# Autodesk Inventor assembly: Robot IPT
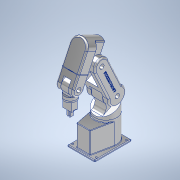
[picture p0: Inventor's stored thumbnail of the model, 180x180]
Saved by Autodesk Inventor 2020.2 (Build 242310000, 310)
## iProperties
Created: 2018-07
Part Number: Robot IPT
Document SubType Name: Assembly
Designer: Power User
Mass: 35329.7 g
Surface Area: 8047.72 cm^2
Volume: 13085.1 cm^3
Density: 2.7 g/cm^3
Author: Power User
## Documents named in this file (10)
- C:\Users\thira\OneDrive\เดสก์ท็อป\INV-01 Intro to Modeling_2020\Robot IPT\Robot IPT.iam
- C:\Users\thira\OneDrive\เดสก์ท็อป\INV-01 Intro to Modeling_2020\Robot IPT\Robot-Base-Model-A.ipt
- C:\Users\thira\OneDrive\เดสก์ท็อป\INV-01 Intro to Modeling_2020\Robot IPT\Robot-Axis1-1.ipt
- C:\Users\thira\OneDrive\เดสก์ท็อป\INV-01 Intro to Modeling_2020\Robot IPT\Robot-Axis1-2.ipt
- C:\Users\thira\OneDrive\เดสก์ท็อป\INV-01 Intro to Modeling_2020\Robot IPT\Robot-Axis1-3.ipt
- C:\Users\thira\OneDrive\เดสก์ท็อป\INV-01 Intro to Modeling_2020\Robot IPT\Robot-Axis1-4.ipt
- C:\Users\thira\OneDrive\เดสก์ท็อป\INV-01 Intro to Modeling_2020\Robot IPT\Robot-Axis1-5.ipt
- C:\Users\thira\OneDrive\เดสก์ท็อป\INV-01 Intro to Modeling_2020\Robot IPT\Robot-Axis1-6.ipt
- C:\Users\thira\OneDrive\เดสก์ท็อป\INV-01 Intro to Modeling_2020\Robot IPT\Robot-Clamp.ipt
- C:\Users\thira\OneDrive\เดสก์ท็อป\INV-01 Intro to Modeling_2020\Robot IPT\Robot-Clamp-Mount.ipt
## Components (10 placed, 9 different names)
1. Robot-Base-Model-A:1 — Rotational:1
2. Robot-Axis1-1:1 — Rotational:1, Rotational:2
3. Robot-Axis1-2:1 — Rotational:2, Rotational:3
4. Robot-Clamp:1 — Mate:1, Mate:2, Slider:1, Mate:5
5. Robot-Clamp-Mount:1 — Rotational:6, Mate:1, Mate:2, Mate:3, Mate:4, Slider:1, Slider:2, Mate:5, Flush:2, Angle:1
6. Robot-Axis1-3:1 — Rotational:3, Rotational:4, Flush:1
7. Robot-Axis1-4:1 — Rotational:4, Rotational:5, Flush:1, Angle:1
8. Robot-Axis1-5:1 — Rotational:5, Rigid:1
9. Robot-Axis1-6:1 — Rigid:1, Rotational:6
10. Robot-Clamp:2 — Mate:3, Mate:4, Slider:2, Flush:2
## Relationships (17: RevoluteJoint 6, Mate 5, Flush 2, TranslationJoint 2, WeldJoint 1, Angle 1)
- Rotational:1 [RevoluteJoint]: Robot-Base-Model-A:1 ↔ Robot-Axis1-1:1
- Rotational:2 [RevoluteJoint]: Robot-Axis1-1:1 ↔ Robot-Axis1-2:1
- Rotational:3 [RevoluteJoint]: Robot-Axis1-2:1 ↔ Robot-Axis1-3:1
- Rotational:4 [RevoluteJoint]: Robot-Axis1-3:1 ↔ Robot-Axis1-4:1
- Rotational:5 [RevoluteJoint]: Robot-Axis1-4:1 ↔ Robot-Axis1-5:1
- Rigid:1 [WeldJoint]: Robot-Axis1-5:1 ↔ Robot-Axis1-6:1
- Flush:1: Robot-Axis1-3:1 ↔ Robot-Axis1-4:1
- Rotational:6 [RevoluteJoint]: Robot-Clamp-Mount:1 ↔ Robot-Axis1-6:1
- Mate:1: Robot-Clamp:1 ↔ Robot-Clamp-Mount:1
- Mate:2: Robot-Clamp:1 ↔ Robot-Clamp-Mount:1
- Mate:3: Robot-Clamp-Mount:1 ↔ Robot-Clamp:2
- Mate:4: Robot-Clamp-Mount:1 ↔ Robot-Clamp:2
- Slider:1 [TranslationJoint]: Robot-Clamp:1 ↔ Robot-Clamp-Mount:1
- Slider:2 [TranslationJoint]: Robot-Clamp-Mount:1 ↔ Robot-Clamp:2
- Mate:5: Robot-Clamp:1 ↔ Robot-Clamp-Mount:1
- Flush:2: Robot-Clamp-Mount:1 ↔ Robot-Clamp:2
- Angle:1: Robot-Clamp-Mount:1 ↔ Robot-Axis1-4:1
